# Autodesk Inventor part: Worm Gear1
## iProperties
Created: 2011-05
Part Number: Worm Gear1
Material: Steel, Mild
Document SubType Name: Modeling
Designer: 904Chiaki
Categories: <?xml version="1.0" encoding="UTF-16"?> <MemberInstance><Categories><FamilyTemplate><FamilyTemplateParameter ValueType="xs:double" Id="1" ObjectReferenceKey="da
Density: 7.86 g/cm^3
Mass: 36271.6 g
Surface Area: 4778.59 cm^2
Volume: 4614.7 cm^3
CustomPartVersion: 1
Author: 904Chiaki
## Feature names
1. Base Body [Revolution]
2. Base Body2 [Revolution]
3. Tooth [Revolution]
4. Tooth Pattern [Circular Pattern]
5. Extrusion1
6. Mirror1
7. Extrusion2
8. Extrusion3
9. Fillet3
10. Extrusion4
11. Extrusion5
12. Chamfer2
13. Fillet4
14. Extrusion6
15. Extrusion7
16. Extrusion8
